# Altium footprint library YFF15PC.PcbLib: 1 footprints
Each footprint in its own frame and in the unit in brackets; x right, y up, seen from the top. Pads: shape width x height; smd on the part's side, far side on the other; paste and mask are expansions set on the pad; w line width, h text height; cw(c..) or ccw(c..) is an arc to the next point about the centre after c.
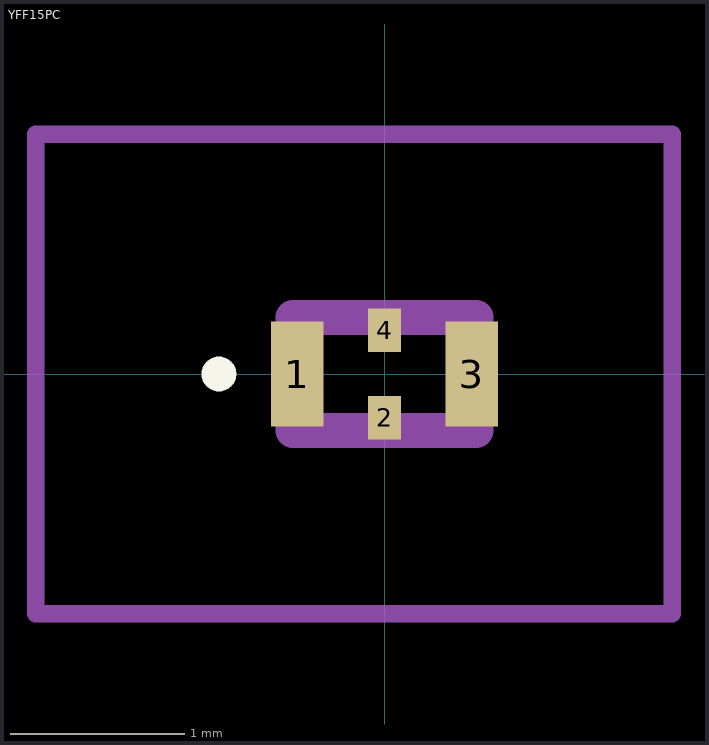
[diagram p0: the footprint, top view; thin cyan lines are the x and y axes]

## YFF15PC [mm]
pads (4):
  rect 0.3x0.6 smd: 1(-0.5,0) 3(0.5,0)
  rect 0.19x0.25 smd: 2(0,-0.25) 4(0,0.25)
Top Overlay:
  lines w0.1: -1,0 -1,0 ; -1,0 ccw(c-0.95,0) -0.9,0 ; -1,0 cw(c-0.95,0) -0.9,0 ; -0.9,0 -0.9,0
Mechanical 15:
  lines w0.2: -0.525,-0.325 0.525,-0.325 0.525,0.325 -0.525,0.325 -0.525,-0.325
Mechanical 20:
  lines w0.1: -2,-1.375 1.65,-1.375 ; -2,-1.375 -2,1.375 ; -2,-1.375 1.65,-1.375 ; -2,-1.375 -2,1.375 ; -2,1.375 1.65,1.375 ; -2,1.375 1.65,1.375 ; 1.65,-1.375 1.65,1.375 ; 1.65,-1.375 1.65,1.375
